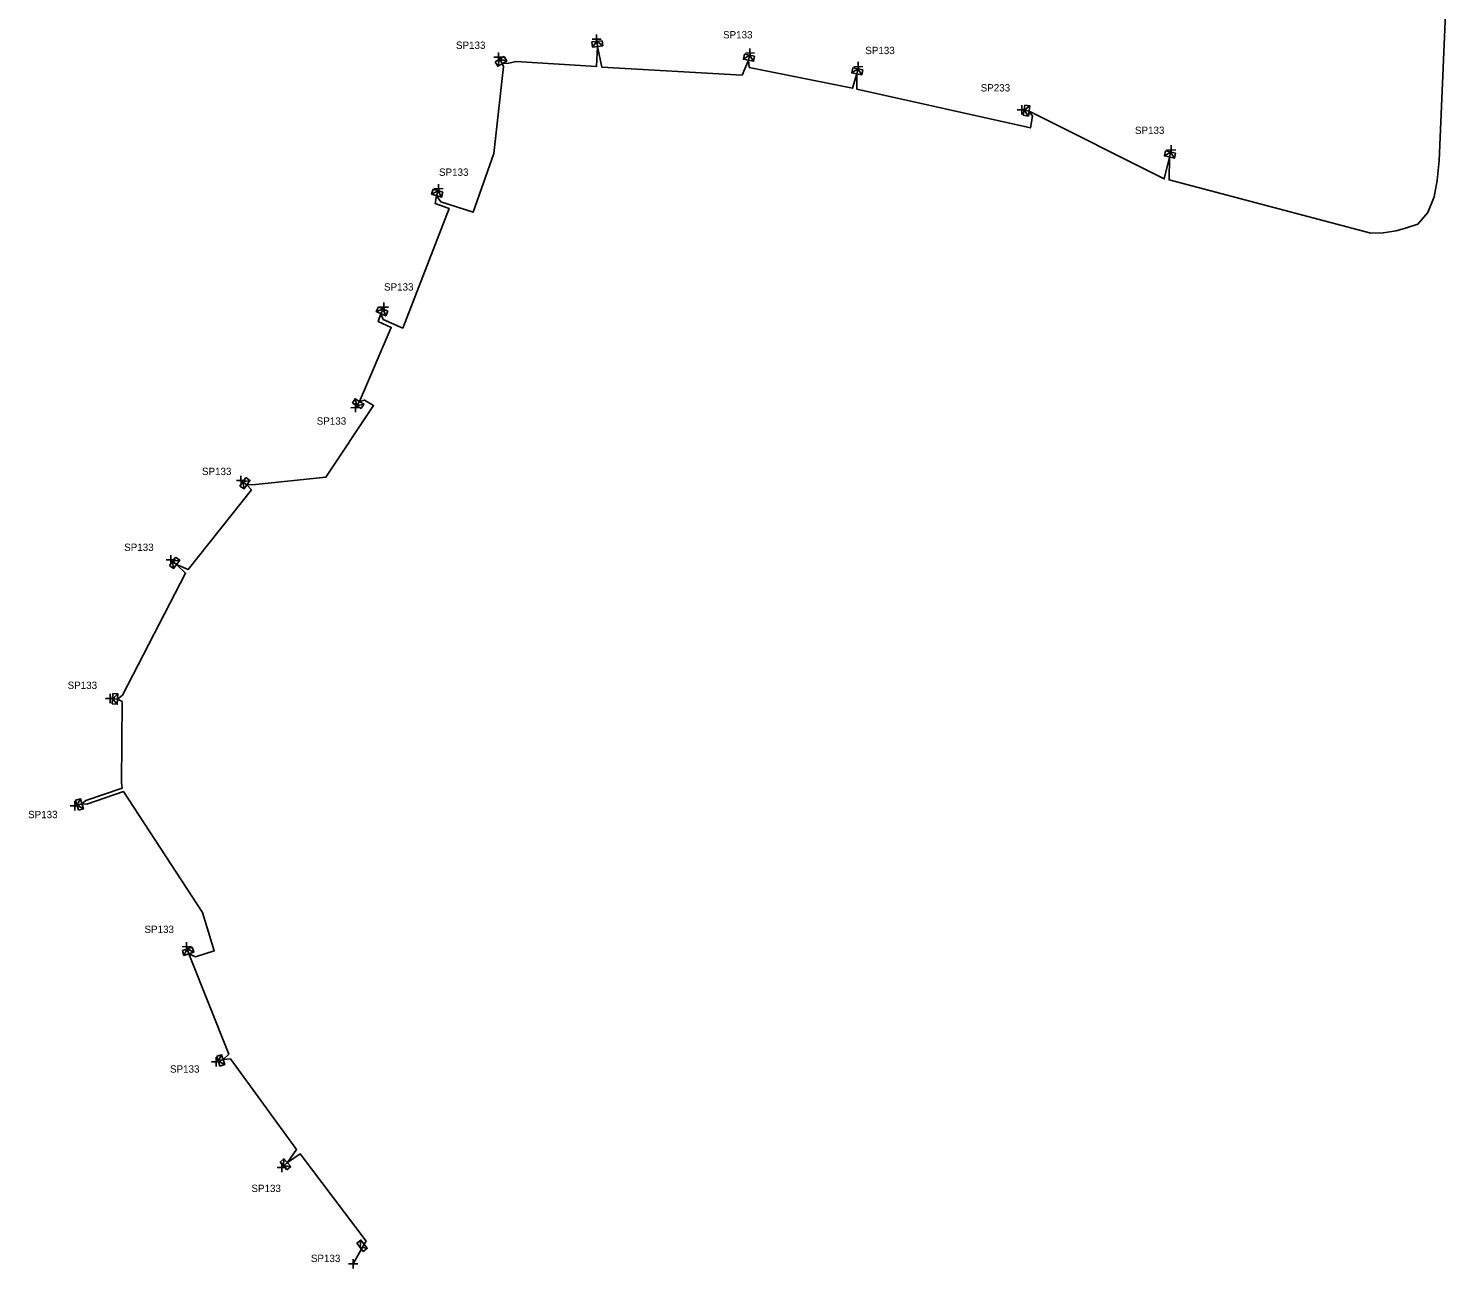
# Model space of a CAD drawing. Extents: x -762503 to -762212, y -1153994 to -1153331.
# Drawn here: x -762425.4 to -762232.1, y -1153994.1 to -1153826.1 of the extents above; entities that cross this region are included whole.
import ezdxf

# ---------------------------------------------------------------- set-up
doc = ezdxf.new("R2010")
doc.units = 0
for name, color, linetype in [('Vrstva 31', 7, 'Continuous'), ('Vrstva 33', 7, 'Continuous'), ('Vrstva 34', 7, 'Continuous'), ('Vrstva 5', 7, 'Continuous'), ('Vrstva 59', 7, 'Continuous')]:
    doc.layers.add(name, color=color, linetype=linetype)

msp = doc.modelspace()

# ---------------------------------------------------------------- linework, layer by layer
at = {"layer": 'Vrstva 31'}
for points in [[(-762347.688, -1153827.779), (-762349.078, -1153827.95)], [(-762347.688, -1153827.779), (-762347.603, -1153828.474), (-762348.992, -1153828.644), (-762349.078, -1153827.95)], [(-762348.383, -1153827.864), (-762348.992, -1153828.644)], [(-762348.383, -1153827.864), (-762347.603, -1153828.474)], [(-762360.962, -1153829.932), (-762362.174, -1153830.632)], [(-762360.962, -1153829.932), (-762360.612, -1153830.538), (-762361.824, -1153831.238), (-762362.174, -1153830.632)], [(-762361.568, -1153830.282), (-762361.824, -1153831.238)], [(-762361.568, -1153830.282), (-762360.612, -1153830.538)], [(-762327.026, -1153829.876), (-762327.16, -1153830.564), (-762328.534, -1153830.296), (-762328.4, -1153829.609)], [(-762327.713, -1153829.743), (-762328.534, -1153830.296)], [(-762327.026, -1153829.876), (-762328.4, -1153829.609)], [(-762327.713, -1153829.743), (-762327.16, -1153830.564)], [(-762312.346, -1153831.717), (-762312.48, -1153832.404), (-762313.854, -1153832.137), (-762313.721, -1153831.45)], [(-762313.033, -1153831.583), (-762313.854, -1153832.137)], [(-762312.346, -1153831.717), (-762313.721, -1153831.45)], [(-762313.033, -1153831.583), (-762312.48, -1153832.404)], [(-762290.392, -1153836.506), (-762290.611, -1153837.889)], [(-762290.392, -1153836.506), (-762289.701, -1153836.615), (-762289.92, -1153837.998), (-762290.611, -1153837.889)], [(-762290.501, -1153837.197), (-762289.701, -1153836.615)], [(-762290.501, -1153837.197), (-762289.92, -1153837.998)], [(-762269.967, -1153843.026), (-762270.125, -1153843.708), (-762271.489, -1153843.393), (-762271.331, -1153842.711)], [(-762270.649, -1153842.868), (-762271.489, -1153843.393)], [(-762269.967, -1153843.026), (-762271.331, -1153842.711)], [(-762270.649, -1153842.868), (-762270.125, -1153843.708)], [(-762369.243, -1153848.326), (-762369.448, -1153848.995), (-762370.787, -1153848.586), (-762370.582, -1153847.917)], [(-762369.913, -1153848.121), (-762370.787, -1153848.586)], [(-762369.243, -1153848.326), (-762370.582, -1153847.917)], [(-762369.913, -1153848.121), (-762369.448, -1153848.995)], [(-762376.723, -1153864.426), (-762377.008, -1153865.065), (-762378.287, -1153864.496), (-762378.002, -1153863.857)], [(-762377.362, -1153864.141), (-762378.287, -1153864.496)], [(-762376.723, -1153864.426), (-762378.002, -1153863.857)], [(-762377.362, -1153864.141), (-762377.008, -1153865.065)], [(-762381.517, -1153876.882), (-762381.146, -1153876.288), (-762379.959, -1153877.03), (-762380.33, -1153877.624)], [(-762381.517, -1153876.882), (-762380.33, -1153877.624)], [(-762380.924, -1153877.253), (-762381.146, -1153876.288)], [(-762380.924, -1153877.253), (-762379.959, -1153877.03)], [(-762395.97, -1153886.973), (-762396.773, -1153888.12)], [(-762395.97, -1153886.973), (-762395.397, -1153887.374), (-762396.2, -1153888.521), (-762396.773, -1153888.12)], [(-762396.372, -1153887.546), (-762395.397, -1153887.374)], [(-762396.372, -1153887.546), (-762396.2, -1153888.521)], [(-762405.466, -1153897.757), (-762406.309, -1153898.875)], [(-762405.466, -1153897.757), (-762404.907, -1153898.178), (-762405.75, -1153899.296), (-762406.309, -1153898.875)], [(-762405.887, -1153898.316), (-762404.907, -1153898.178)], [(-762405.887, -1153898.316), (-762405.75, -1153899.296)], [(-762413.99, -1153916.249), (-762414.088, -1153917.646)], [(-762413.99, -1153916.249), (-762413.292, -1153916.298), (-762413.389, -1153917.695), (-762414.088, -1153917.646)], [(-762414.039, -1153916.948), (-762413.292, -1153916.298)], [(-762414.039, -1153916.948), (-762413.389, -1153917.695)], [(-762419.027, -1153930.707), (-762418.354, -1153930.514), (-762417.969, -1153931.86), (-762418.641, -1153932.053)], [(-762419.027, -1153930.707), (-762418.641, -1153932.053)], [(-762418.834, -1153931.38), (-762418.354, -1153930.514)], [(-762418.834, -1153931.38), (-762417.969, -1153931.86)], [(-762403.228, -1153950.627), (-762404.559, -1153951.059)], [(-762403.228, -1153950.627), (-762403.011, -1153951.292), (-762404.343, -1153951.725), (-762404.559, -1153951.059)], [(-762403.893, -1153950.843), (-762404.343, -1153951.725)], [(-762403.893, -1153950.843), (-762403.011, -1153951.292)], [(-762399.903, -1153965.398), (-762399.238, -1153965.182), (-762398.805, -1153966.513), (-762399.471, -1153966.73)], [(-762399.903, -1153965.398), (-762399.471, -1153966.73)], [(-762399.687, -1153966.064), (-762399.238, -1153965.182)], [(-762399.687, -1153966.064), (-762398.805, -1153966.513)], [(-762391.321, -1153979.736), (-762390.801, -1153979.268), (-762389.864, -1153980.308), (-762390.384, -1153980.777)], [(-762391.321, -1153979.736), (-762390.384, -1153980.777)], [(-762390.853, -1153980.257), (-762390.801, -1153979.268)], [(-762390.853, -1153980.257), (-762389.864, -1153980.308)], [(-762380.915, -1153990.727), (-762380.363, -1153990.296), (-762379.501, -1153991.399), (-762380.053, -1153991.83)], [(-762380.915, -1153990.727), (-762380.053, -1153991.83)], [(-762380.484, -1153991.278), (-762380.363, -1153990.296)], [(-762380.484, -1153991.278), (-762379.501, -1153991.399)]]:
    msp.add_lwpolyline(points, dxfattribs=at)
at = {"layer": 'Vrstva 34'}
for points in [[(-762348.409, -1153828.195), (-762348.431, -1153826.945)], [(-762349.045, -1153827.581), (-762347.795, -1153827.559)], [(-762327.629, -1153830.075), (-762327.651, -1153828.825)], [(-762362.335, -1153830.031), (-762361.085, -1153830.009)], [(-762361.699, -1153830.645), (-762361.721, -1153829.395)], [(-762328.265, -1153829.461), (-762327.015, -1153829.439)], [(-762312.949, -1153831.915), (-762312.971, -1153830.665)], [(-762313.585, -1153831.301), (-762312.335, -1153831.279)], [(-762290.789, -1153837.765), (-762290.811, -1153836.515)], [(-762291.425, -1153837.151), (-762290.175, -1153837.129)], [(-762271.195, -1153842.591), (-762269.945, -1153842.569)], [(-762270.559, -1153843.205), (-762270.581, -1153841.955)], [(-762370.445, -1153847.841), (-762369.195, -1153847.819)], [(-762369.809, -1153848.455), (-762369.831, -1153847.205)], [(-762377.855, -1153863.891), (-762376.605, -1153863.869)], [(-762377.219, -1153864.505), (-762377.241, -1153863.255)], [(-762381.715, -1153877.521), (-762380.465, -1153877.499)], [(-762381.079, -1153878.135), (-762381.101, -1153876.885)], [(-762396.599, -1153887.995), (-762396.621, -1153886.745)], [(-762397.235, -1153887.381), (-762395.985, -1153887.359)], [(-762406.755, -1153898.141), (-762405.505, -1153898.119)], [(-762406.119, -1153898.755), (-762406.141, -1153897.505)], [(-762414.329, -1153917.535), (-762414.351, -1153916.285)], [(-762414.965, -1153916.921), (-762413.715, -1153916.899)], [(-762419.755, -1153931.471), (-762418.505, -1153931.449)], [(-762419.119, -1153932.085), (-762419.141, -1153930.835)], [(-762404.605, -1153950.561), (-762403.355, -1153950.539)], [(-762403.969, -1153951.175), (-762403.991, -1153949.925)], [(-762400.605, -1153966.161), (-762399.355, -1153966.139)], [(-762399.969, -1153966.775), (-762399.991, -1153965.525)], [(-762391.069, -1153981.085), (-762391.091, -1153979.835)], [(-762391.705, -1153980.471), (-762390.455, -1153980.449)], [(-762382.035, -1153993.531), (-762380.785, -1153993.509)], [(-762381.399, -1153994.145), (-762381.421, -1153992.895)]]:
    msp.add_lwpolyline(points, dxfattribs=at)
at = {"layer": 'Vrstva 5'}
msp.add_lwpolyline([(-762232.05, -1153792.6), (-762234.26, -1153844.02), (-762234.53, -1153846.73), (-762234.93, -1153848.94), (-762235.81, -1153851.07), (-762237.14, -1153852.62), (-762238.83, -1153853.2), (-762240.07, -1153853.55), (-762241.84, -1153853.82), (-762243.52, -1153853.86), (-762270.86, -1153846.64), (-762270.81, -1153843.55), (-762271.52, -1153846.51), (-762289.81, -1153837.31), (-762289.37, -1153838), (-762289.64, -1153839.59), (-762313.16, -1153834.36), (-762313.17, -1153832.27), (-762313.74, -1153834.23), (-762327.74, -1153831.39), (-762327.85, -1153830.43), (-762328.71, -1153832.45), (-762347.72, -1153831.35), (-762348.3, -1153828.56), (-762348.43, -1153831.26), (-762359.33, -1153830.59), (-762360.3, -1153830.81), (-762361.22, -1153830.89), (-762361.05, -1153831.26), (-762362.34, -1153843.05), (-762365.13, -1153851.03), (-762369.52, -1153849.61), (-762370.13, -1153848.79), (-762370.31, -1153849.83), (-762368.41, -1153850.5), (-762374.7, -1153866.72), (-762377.36, -1153865.57), (-762377.65, -1153864.78), (-762378.02, -1153865.83), (-762376.25, -1153866.63), (-762380.55, -1153876.66), (-762379.88, -1153876.47), (-762378.64, -1153877.23), (-762385.11, -1153886.93), (-762394.63, -1153887.91), (-762395.8, -1153887.95), (-762395.21, -1153888.62), (-762403.76, -1153899.43), (-762405.33, -1153898.74), (-762404.12, -1153899.92), (-762412.67, -1153916.46), (-762413.34, -1153916.99), (-762412.71, -1153917.34), (-762412.8, -1153928.34), (-762412.71, -1153929.05), (-762417.65, -1153930.72), (-762418.16, -1153931.19), (-762417.52, -1153931.22), (-762412.53, -1153929.53), (-762401.81, -1153945.89), (-762400.26, -1153951.12), (-762402.79, -1153951.92), (-762403.68, -1153951.51), (-762398.27, -1153965.13), (-762399.02, -1153965.85), (-762398.05, -1153965.75), (-762389.1, -1153978.03), (-762390.33, -1153979.79), (-762388.61, -1153978.6), (-762379.66, -1153990.44), (-762379.93, -1153990.85)], dxfattribs=at)
at = {"layer": 'Vrstva 59'}
for points in [[(-762348.3, -1153828.56), (-762348.42, -1153827.57)], [(-762361.22, -1153830.89), (-762361.71, -1153830.02)], [(-762327.85, -1153830.43), (-762327.64, -1153829.45)], [(-762313.17, -1153832.27), (-762312.96, -1153831.29)], [(-762289.81, -1153837.31), (-762290.8, -1153837.14)], [(-762270.81, -1153843.55), (-762270.57, -1153842.58)], [(-762370.12, -1153848.79), (-762369.82, -1153847.83)], [(-762377.65, -1153864.78), (-762377.23, -1153863.88)], [(-762380.55, -1153876.66), (-762381.09, -1153877.51)], [(-762395.8, -1153887.95), (-762396.61, -1153887.37)], [(-762405.33, -1153898.74), (-762406.13, -1153898.13)], [(-762413.34, -1153917), (-762414.34, -1153916.91)], [(-762418.17, -1153931.19), (-762419.13, -1153931.46)], [(-762403.68, -1153951.51), (-762403.98, -1153950.55)], [(-762399.02, -1153965.85), (-762399.98, -1153966.15)], [(-762390.33, -1153979.79), (-762391.08, -1153980.46)], [(-762379.93, -1153990.85), (-762381.41, -1153993.52)]]:
    msp.add_lwpolyline(points, dxfattribs=at)

# ---------------------------------------------------------------- texts
at = {"layer": 'Vrstva 33'}
for s, p in [('SP133', (-762331.29, -1153827.47)), ('SP133', (-762367.48, -1153828.89)), ('SP133', (-762312.02, -1153829.6)), ('SP233', (-762296.38, -1153834.66)), ('SP133', (-762275.48, -1153840.42)), ('SP133', (-762369.78, -1153846.09)), ('SP133', (-762377.23, -1153861.64)), ('SP133', (-762386.35, -1153879.81)), ('SP133', (-762401.9, -1153886.64)), ('SP133', (-762412.44, -1153896.92)), ('SP133', (-762420.1, -1153915.62)), ('SP133', (-762425.46, -1153933.13)), ('SP133', (-762409.69, -1153948.69)), ('SP133', (-762406.23, -1153967.61)), ('SP133', (-762395.2, -1153983.79)), ('SP133', (-762387.14, -1153993.27))]:
    msp.add_text(s, height=0.9943, dxfattribs=at).set_placement(p)

doc.saveas('drawing.dxf')
